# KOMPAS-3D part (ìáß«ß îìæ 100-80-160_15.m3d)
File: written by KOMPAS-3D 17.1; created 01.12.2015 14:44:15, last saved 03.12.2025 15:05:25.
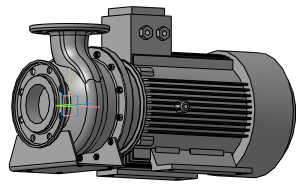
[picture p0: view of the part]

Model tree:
1. Операция без истории:3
